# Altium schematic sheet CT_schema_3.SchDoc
size 276 x 169 mm
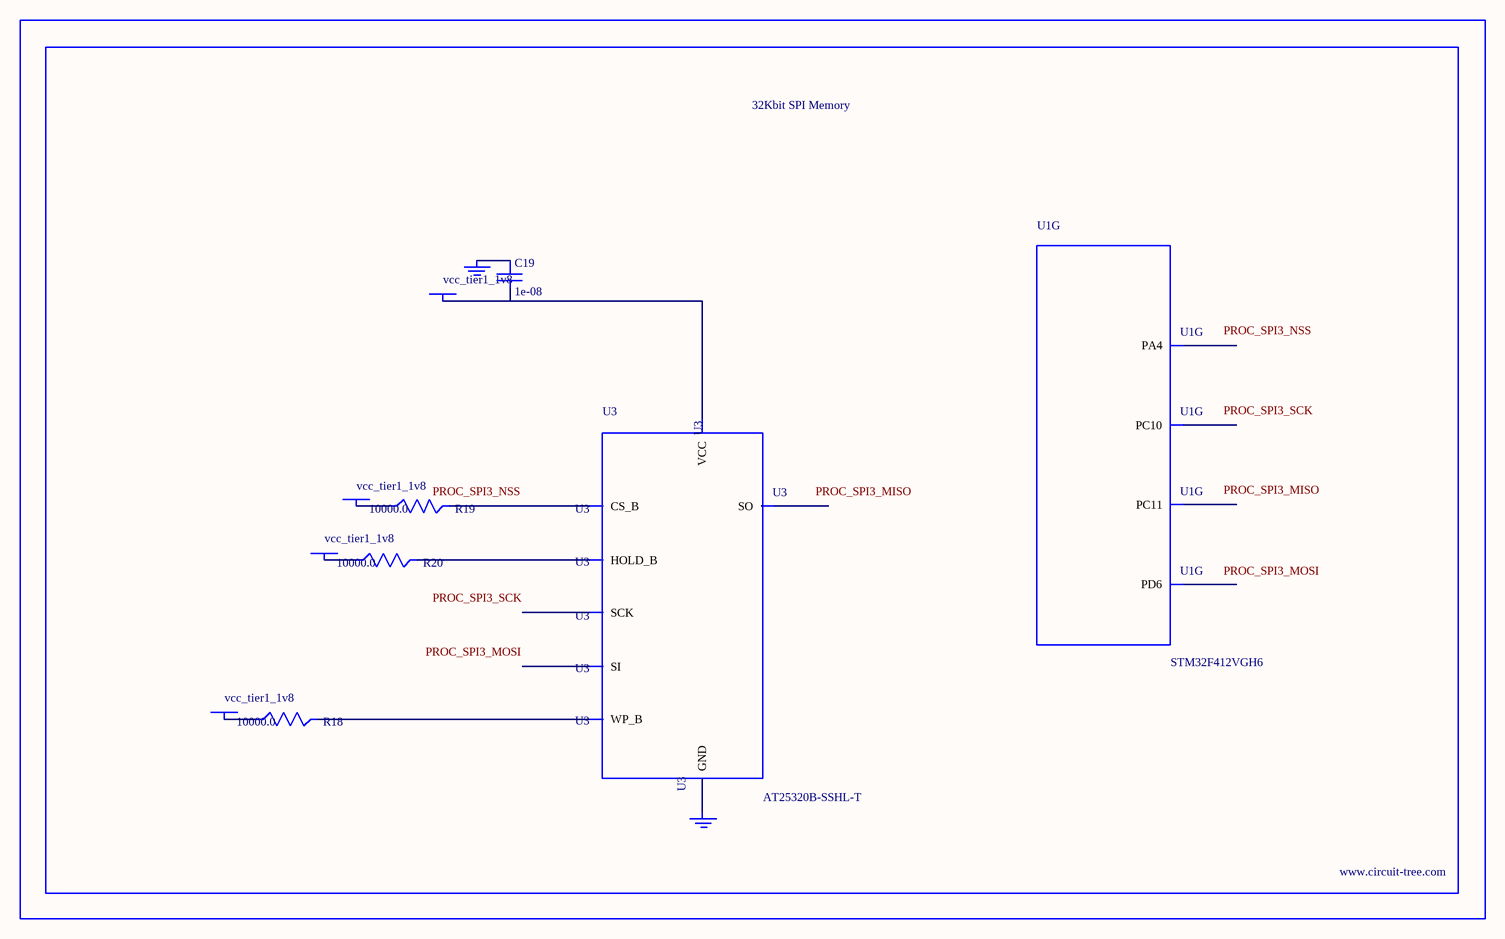
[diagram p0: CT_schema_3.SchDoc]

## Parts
BORDER2  (no value)
C19  1e-08  [C0402]
GND_INSTANCE_2_0  (no value)
GND_INSTANCE_2_1  (no value)
POWER_INSTANCE_2_0  vcc_tier1_1v8
POWER_INSTANCE_2_1  vcc_tier1_1v8
POWER_INSTANCE_2_2  vcc_tier1_1v8
POWER_INSTANCE_2_3  vcc_tier1_1v8
R18  10000.0  [R0603]
R19  10000.0  [R0603]
R20  10000.0  [R0603]
U1  STM32F412VGH6  [UFBGA100]  (part G of 11)
U3  AT25320B-SSHL-T  [SOIC-8]

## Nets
NetC19_1: C19.1 GND_INSTANCE_2_0.0(GND)
NetC19_2: C19.2 POWER_INSTANCE_2_3.0(PWR) U3.8(VCC)
NetGND_INSTANCE_2_1_0: GND_INSTANCE_2_1.0(GND) U3.4(GND)
NetPOWER_INSTANCE_2_0_0: POWER_INSTANCE_2_0.0(PWR) R19.1
NetPOWER_INSTANCE_2_1_0: POWER_INSTANCE_2_1.0(PWR) R18.1
NetPOWER_INSTANCE_2_2_0: POWER_INSTANCE_2_2.0(PWR) R20.1
NetR18_2: R18.2 U3.3(WP_B)
NetR19_2: R19.2 U3.1(CS_B)
NetR20_2: R20.2 U3.7(HOLD_B)

Not connected (* = marked no-connect by the designer): U1 B6(PD6) B11(PC10) C10(PC11) M3(PA4); U3 2(SO) 5(SI) 6(SCK)

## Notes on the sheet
- Labels drawn without touching a wire or pin: PROC_SPI3_MISO, PROC_SPI3_MOSI, PROC_SPI3_NSS, PROC_SPI3_SCK

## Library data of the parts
BORDER2 = BORDER_PAGE2
C19 = C0402C103K3RAC
GND_INSTANCE_2_0 GND_INSTANCE_2_1 = GND
POWER_INSTANCE_2_0-POWER_INSTANCE_2_3 = PWR
R18-R20 = RC0603JR-0710KL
